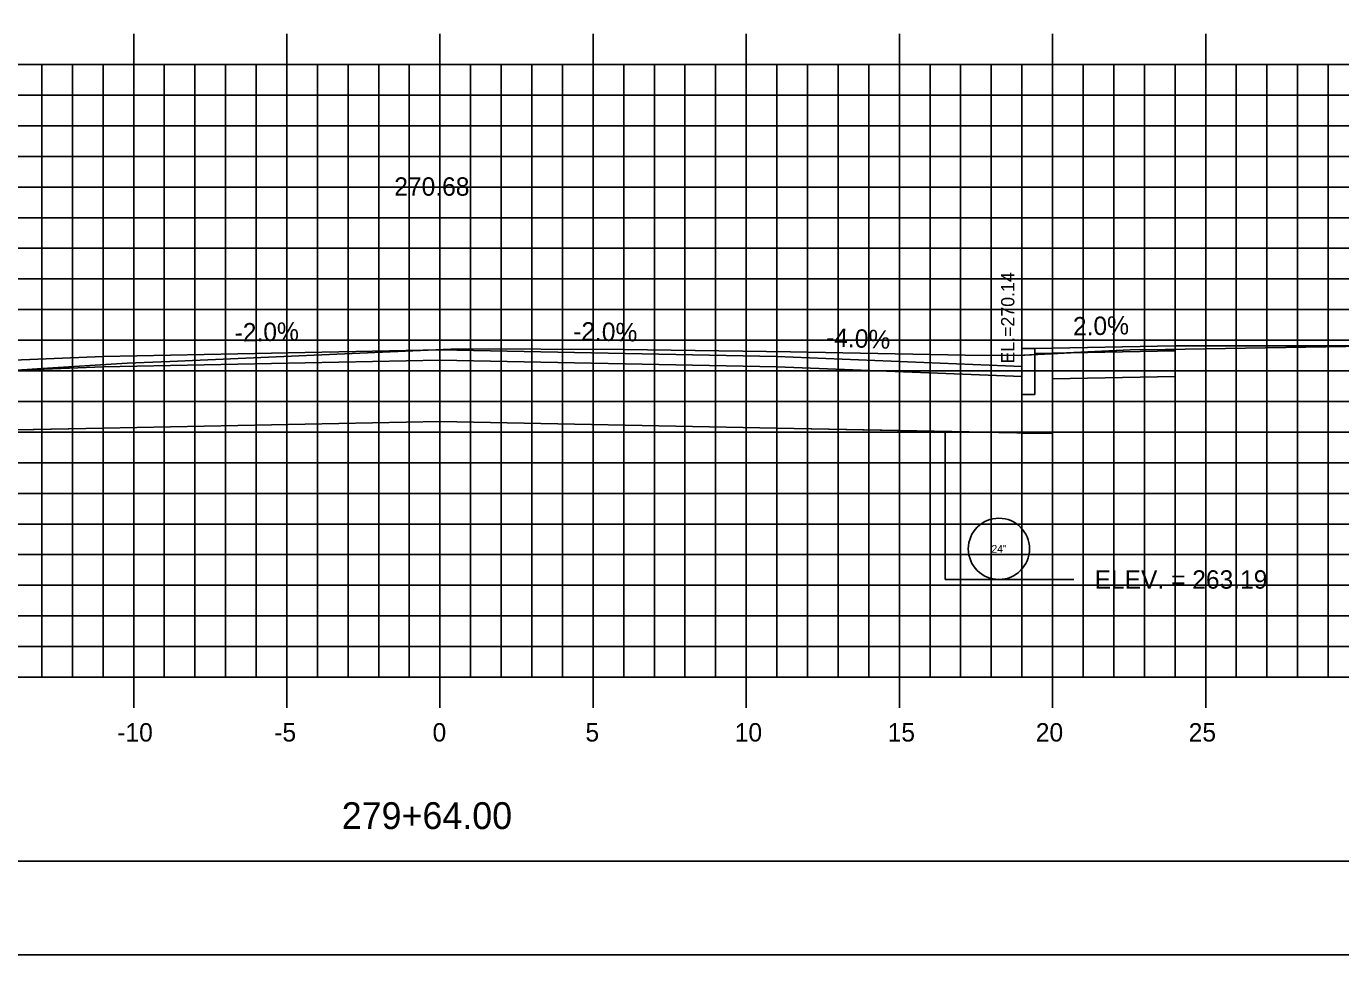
# Model space of a CAD drawing. Extents: x 855121 to 855291, y 366268 to 366378.
# Drawn here: x 855190.94 to 855233.85, y 366268.18 to 366298.48 of the extents above; entities that cross this region are included whole.
import ezdxf

# ---------------------------------------------------------------- set-up
doc = ezdxf.new("R2010")
doc.units = 0
for name, color, linetype in [('ANNOTATION', 7, 'Continuous'), ('BORDER', 7, 'Continuous'), ('D_Curb_Type_1_Rt', 7, 'Continuous'), ('D_Roadway_Centerline_Text', 7, 'Continuous'), ('D_Roadway_Drive_SubGrade', 7, 'Continuous'), ('D_Roadway_Edge_Shoulder', 7, 'Continuous'), ('D_Roadway_FinishedGrade', 7, 'Continuous'), ('D_Roadway_Sidewalks_Paved', 7, 'Continuous'), ('D_Roadway_SubGrade', 7, 'Continuous'), ('D_Text_Standard', 7, 'Continuous'), ('H_V ANNOTATION', 7, 'Continuous'), ('JUNK COM EXC', 7, 'Continuous'), ('junk strct exc', 7, 'Continuous'), ('MAJOR', 7, 'Continuous'), ('MINOR', 7, 'Continuous'), ('PDRAIN', 7, 'Continuous'), ('PLOT BOUNDARY', 7, 'Continuous'), ('S_Roadway_Centerline', 7, 'Continuous')]:
    doc.layers.add(name, color=color, linetype=linetype)

msp = doc.modelspace()

# ---------------------------------------------------------------- linework, layer by layer
at = {"layer": 'BORDER'}
msp.add_line((855129.442, 366271.236), (855289.442, 366271.236), dxfattribs=at)
at = {"layer": 'D_Curb_Type_1_Rt'}
msp.add_lwpolyline([(855223.859, 366287.964), (855223.859, 366286.464), (855223.442, 366286.464), (855223.442, 366287.964)], close=True, dxfattribs=at)
at = {"layer": 'D_Roadway_Drive_SubGrade'}
msp.add_line((855223.442, 366285.207), (855224.442, 366285.187), dxfattribs=at)
at = {"layer": 'D_Roadway_Edge_Shoulder'}
msp.add_line((855223.442, 366287.381), (855223.442, 366287.048), dxfattribs=at)
msp.add_lwpolyline([(855185.442, 366287.381), (855193.442, 366287.701), (855204.442, 366287.921), (855215.442, 366287.701), (855223.442, 366287.381)], dxfattribs=at)
at = {"layer": 'D_Roadway_FinishedGrade'}
msp.add_line((855228.448, 366288.056), (855235.338, 366288.056), dxfattribs=at)
at = {"layer": 'D_Roadway_Sidewalks_Paved'}
msp.add_lwpolyline([(855223.859, 366287.964), (855228.448, 366288.056), (855228.448, 366287.889), (855223.859, 366287.797)], close=True, dxfattribs=at)
at = {"layer": 'D_Roadway_SubGrade'}
for points in [[(855193.442, 366285.368), (855193.442, 366287.368), (855204.442, 366287.588), (855215.442, 366287.368), (855215.442, 366285.368), (855204.442, 366285.588)], [(855193.442, 366287.368), (855185.442, 366287.048), (855185.442, 366285.208), (855193.442, 366285.368)], [(855215.442, 366287.368), (855223.442, 366287.048), (855223.442, 366285.208), (855215.442, 366285.368)]]:
    msp.add_lwpolyline(points, close=True, dxfattribs=at)
msp.add_lwpolyline([(855228.448, 366287.889), (855228.448, 366287.055), (855224.443, 366286.975), (855224.443, 366285.187), (855223.442, 366285.207)], dxfattribs=at)
at = {"layer": 'D_Text_Standard'}
msp.add_lwpolyline([(855224.442, 366280.426), (855224.454, 366280.426), (855225.134, 366280.426)], dxfattribs=at)
at = {"layer": 'JUNK COM EXC'}
msp.add_lwpolyline([(855184.442, 366287.392), (855184.442, 366285.187), (855193.442, 366285.368), (855204.442, 366285.588), (855215.442, 366285.368), (855224.442, 366285.187), (855224.443, 366286.975), (855228.448, 366287.055), (855228.448, 366287.936), (855226.977, 366287.924), (855224.442, 366287.797), (855223.319, 366287.74), (855221.589, 366287.744), (855215.888, 366287.856), (855210.431, 366287.929), (855205.043, 366287.951), (855195.623, 366287.546), (855194.227, 366287.484), (855191.456, 366287.318), (855188.148, 366287.092), (855186.064, 366287.235)], close=True, dxfattribs=at)
at = {"layer": 'junk strct exc'}
msp.add_lwpolyline([(855220.942, 366285.258), (855220.942, 366280.426), (855224.442, 366280.426), (855224.442, 366285.187)], close=True, dxfattribs=at)
at = {"layer": 'MAJOR'}
for p, q in [((855194.442, 366298.238), (855194.442, 366297.236)), ((855199.442, 366298.238), (855199.442, 366297.236)), ((855204.442, 366298.238), (855204.442, 366297.236)), ((855209.442, 366298.238), (855209.442, 366297.236)), ((855214.442, 366298.238), (855214.442, 366297.236)), ((855219.442, 366298.238), (855219.442, 366297.236)), ((855224.442, 366298.238), (855224.442, 366297.236)), ((855229.442, 366298.238), (855229.442, 366297.236)), ((855134.442, 366297.236), (855274.442, 366297.236)), ((855134.442, 366297.236), (855274.442, 366297.236)), ((855194.442, 366277.236), (855194.442, 366297.236)), ((855199.442, 366277.236), (855199.442, 366297.236)), ((855204.442, 366277.236), (855204.442, 366297.236)), ((855209.442, 366277.236), (855209.442, 366297.236)), ((855214.442, 366277.236), (855214.442, 366297.236)), ((855219.442, 366277.236), (855219.442, 366297.236)), ((855224.442, 366277.236), (855224.442, 366297.236)), ((855229.442, 366277.236), (855229.442, 366297.236)), ((855134.442, 366292.236), (855274.442, 366292.236)), ((855134.442, 366287.236), (855274.442, 366287.236)), ((855134.442, 366282.236), (855274.442, 366282.236)), ((855134.442, 366277.236), (855274.442, 366277.236)), ((855134.442, 366277.236), (855274.442, 366277.236)), ((855194.442, 366276.234), (855194.442, 366277.236)), ((855199.442, 366276.234), (855199.442, 366277.236)), ((855204.442, 366276.234), (855204.442, 366277.236)), ((855209.442, 366276.234), (855209.442, 366277.236)), ((855214.442, 366276.234), (855214.442, 366277.236)), ((855219.442, 366276.234), (855219.442, 366277.236)), ((855224.442, 366276.234), (855224.442, 366277.236)), ((855229.442, 366276.234), (855229.442, 366277.236))]:
    msp.add_line(p, q, dxfattribs=at)
at = {"layer": 'MINOR'}
for p, q in [((855191.442, 366277.236), (855191.442, 366297.236)), ((855192.442, 366277.236), (855192.442, 366297.236)), ((855193.442, 366277.236), (855193.442, 366297.236)), ((855195.442, 366277.236), (855195.442, 366297.236)), ((855196.442, 366277.236), (855196.442, 366297.236)), ((855197.442, 366277.236), (855197.442, 366297.236)), ((855198.442, 366277.236), (855198.442, 366297.236)), ((855200.442, 366277.236), (855200.442, 366297.236)), ((855201.442, 366277.236), (855201.442, 366297.236)), ((855202.442, 366277.236), (855202.442, 366297.236)), ((855203.442, 366277.236), (855203.442, 366297.236)), ((855205.442, 366277.236), (855205.442, 366297.236)), ((855206.442, 366277.236), (855206.442, 366297.236)), ((855207.442, 366277.236), (855207.442, 366297.236)), ((855208.442, 366277.236), (855208.442, 366297.236)), ((855210.442, 366277.236), (855210.442, 366297.236)), ((855211.442, 366277.236), (855211.442, 366297.236)), ((855212.442, 366277.236), (855212.442, 366297.236)), ((855213.442, 366277.236), (855213.442, 366297.236)), ((855215.442, 366277.236), (855215.442, 366297.236)), ((855216.442, 366277.236), (855216.442, 366297.236)), ((855217.442, 366277.236), (855217.442, 366297.236)), ((855218.442, 366277.236), (855218.442, 366297.236)), ((855220.442, 366277.236), (855220.442, 366297.236)), ((855221.442, 366277.236), (855221.442, 366297.236)), ((855222.442, 366277.236), (855222.442, 366297.236)), ((855223.442, 366277.236), (855223.442, 366297.236)), ((855225.442, 366277.236), (855225.442, 366297.236)), ((855226.442, 366277.236), (855226.442, 366297.236)), ((855227.442, 366277.236), (855227.442, 366297.236)), ((855228.442, 366277.236), (855228.442, 366297.236)), ((855230.442, 366277.236), (855230.442, 366297.236)), ((855231.442, 366277.236), (855231.442, 366297.236)), ((855232.442, 366277.236), (855232.442, 366297.236)), ((855233.442, 366277.236), (855233.442, 366297.236)), ((855134.442, 366296.236), (855274.442, 366296.236)), ((855134.442, 366295.236), (855274.442, 366295.236)), ((855134.442, 366294.236), (855274.442, 366294.236)), ((855134.442, 366293.236), (855274.442, 366293.236)), ((855134.442, 366291.236), (855274.442, 366291.236)), ((855134.442, 366290.236), (855274.442, 366290.236)), ((855134.442, 366289.236), (855274.442, 366289.236)), ((855134.442, 366288.236), (855274.442, 366288.236)), ((855134.442, 366286.236), (855274.442, 366286.236)), ((855134.442, 366285.236), (855274.442, 366285.236)), ((855134.442, 366284.236), (855274.442, 366284.236)), ((855134.442, 366283.236), (855274.442, 366283.236)), ((855134.442, 366281.236), (855274.442, 366281.236)), ((855134.442, 366280.236), (855274.442, 366280.236)), ((855134.442, 366279.236), (855274.442, 366279.236)), ((855134.442, 366278.236), (855274.442, 366278.236))]:
    msp.add_line(p, q, dxfattribs=at)
at = {"layer": 'PDRAIN'}
msp.add_lwpolyline([(855220.942, 366285.258), (855220.942, 366280.426), (855224.442, 366280.426), (855224.442, 366285.187)], dxfattribs=at)
msp.add_circle((855222.692, 366281.426), 1, dxfattribs=at)
at = {"layer": 'PLOT BOUNDARY'}
msp.add_lwpolyline([(855121.349, 366268.177), (855291.349, 366268.177), (855291.349, 366378.177), (855121.349, 366378.177)], close=True, dxfattribs=at)
at = {"layer": 'S_Roadway_Centerline'}
msp.add_lwpolyline([(855157.182, 366287.226), (855171.097, 366287.369), (855184.381, 366287.398), (855186.064, 366287.235), (855188.148, 366287.092), (855191.456, 366287.318), (855194.227, 366287.484), (855195.623, 366287.546), (855205.043, 366287.951), (855210.431, 366287.929), (855215.888, 366287.856), (855221.589, 366287.744), (855223.319, 366287.74), (855226.977, 366287.924), (855228.12, 366287.931), (855237.955, 366288.101)], dxfattribs=at)

# ---------------------------------------------------------------- texts
at = {"layer": 'ANNOTATION'}
for s, rotation, p in [('-2.0%', 1.1458, (855197.745, 366288.187)), ('-2.0%', 358.8542, (855208.785, 366288.234)), ('2.0%', 1.1485, (855225.115, 366288.389)), ('-4.0%', 357.7094, (855217.039, 366288.037))]:
    msp.add_text(s, height=0.6, rotation=rotation, dxfattribs=at).set_placement(p)
at = {"layer": 'D_Roadway_Centerline_Text'}
msp.add_text('270.68', height=0.6, dxfattribs=at).set_placement((855202.951, 366292.953))
at = {"layer": 'D_Text_Standard'}
msp.add_text(' EL.=270.14', height=0.4335, rotation=90, dxfattribs=at).set_placement((855223.196, 366287.312))
msp.add_text('ELEV. = 263.19', height=0.6, dxfattribs=at).set_placement((855225.814, 366280.126))
at = {"layer": 'H_V ANNOTATION'}
for s, height, p in [('-10', 0.6, (855193.907, 366275.136)), ('-5', 0.6, (855199.032, 366275.136)), ('0', 0.6, (855204.201, 366275.136)), ('5', 0.6, (855209.193, 366275.136)), ('10', 0.6, (855214.067, 366275.136)), ('15', 0.6, (855219.059, 366275.136)), ('20', 0.6, (855223.896, 366275.136)), ('25', 0.6, (855228.888, 366275.136)), ('279+64.00', 0.875, (855201.235, 366272.28))]:
    msp.add_text(s, height=height, dxfattribs=at).set_placement(p)
at = {"layer": 'PDRAIN'}
msp.add_text('24"', height=0.25, dxfattribs=at).set_placement((855222.45, 366281.301))
at = {"layer": 'S_Roadway_Centerline'}
for s, p in [('C', (855205.038, 366287.951)), ('L', (855205.043, 366287.944))]:
    msp.add_text(s, height=0.0146, dxfattribs=at).set_placement(p)

doc.saveas('drawing.dxf')
